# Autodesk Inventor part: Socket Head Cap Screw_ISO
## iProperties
Created: 2011-02
Part Number: Socket Head Cap Screw_ISO
Document SubType Name: Modeling
Designer: eric
Density: 1 g/cm^3
Author: eric
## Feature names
1. Base1
